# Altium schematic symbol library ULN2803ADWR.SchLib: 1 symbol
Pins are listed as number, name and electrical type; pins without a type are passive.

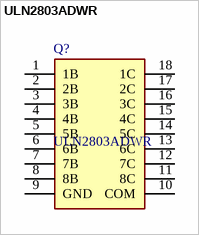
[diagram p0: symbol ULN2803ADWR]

## ULN2803ADWR
designator Q?
Darlington Transistor Array; Manufacturer_Name: Texas Instruments; Geometry.Height: 2.65mm
footprint SOIC127P1030X265-18N
pins: 1 1B, 2 2B, 3 3B, 4 4B, 5 5B, 6 6B, 7 7B, 8 8B, 9 GND, 10 COM, 11 8C, 12 7C, 13 6C, 14 5C, 15 4C, 16 3C, 17 2C, 18 1C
